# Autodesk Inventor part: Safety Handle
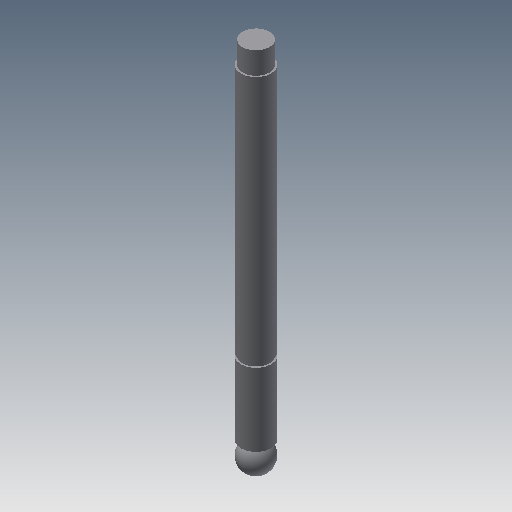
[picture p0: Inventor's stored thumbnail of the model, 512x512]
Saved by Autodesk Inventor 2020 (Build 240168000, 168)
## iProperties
Created: 2002-02
Part Number: Safety Handle
Document SubType Name: Modeling
Designer: ***
Density: 1 g/cm^3
Material: Generic
Appearance: Default
Control State: 0
Master: False
Checked Out: False
Shininess: 77.0
Length Units: 11269
Angle Units: 11279
Time Units: 11290
Mass Units: 11283
Length Display Precision: 3
Angle Display Precision: 2
Density: 0.0
Volumn: 0.0
Area: 0.0
PropertySet Name: Model Information
Author: ***
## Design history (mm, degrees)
sketch "Sketch1"
  geometry: L1 (0, 205)-(8, 205); L2 (8, 205)-(8, 192); L3 (8, 192)-(9, 192); L4 (9, 192)-(9, 45); L5 (9, 45)-(8, 45); L6 (8, 45)-(8, 43); L7 (8, 43)-(9, 43); L8 (9, 43)-(9, 0); L9 (9, 0)-(0, 0); L10 (0, 0)-(0, 205)
  constraints: 20 end point, 7 parallel, 1 collinear, 1 horizontal, 1 perpendicular
  dimensions: "d0" = 13 distance of L1.end L2.end; "d1" = 2 distance of L4.end L7.end; "d2" = 43 distance of L7.end L8.end; "d3" = 205 distance of L9.end L1.start; "d4" = 16 diameter of L2 L10; "d5" = 18 diameter of L4 L10; "d6" = 16 diameter of L6.end L10
revolve "Revolution1" sketch "Sketch1" stored, may be unused: angle "d7" = 90 deg
sketch "Sketch2"
  geometry: L1 (0, 1)-(0, -17); L2 (-9, 0)-(9, 0) reference; A1 r 9 centre (0, -8) between (0, -17) and (0, 1)
  constraints: 2 end point, 2 point on circle, 1 centre point, 1 midpoint, 1 vertical
  dimensions: "d8" = 9 radius of A1; "d9" = 1 distance from line of L2 L1.start
revolve "Revolution2" sketch "Sketch2" stored, may be unused: angle "d10" = 90 deg
body "Solid1"
